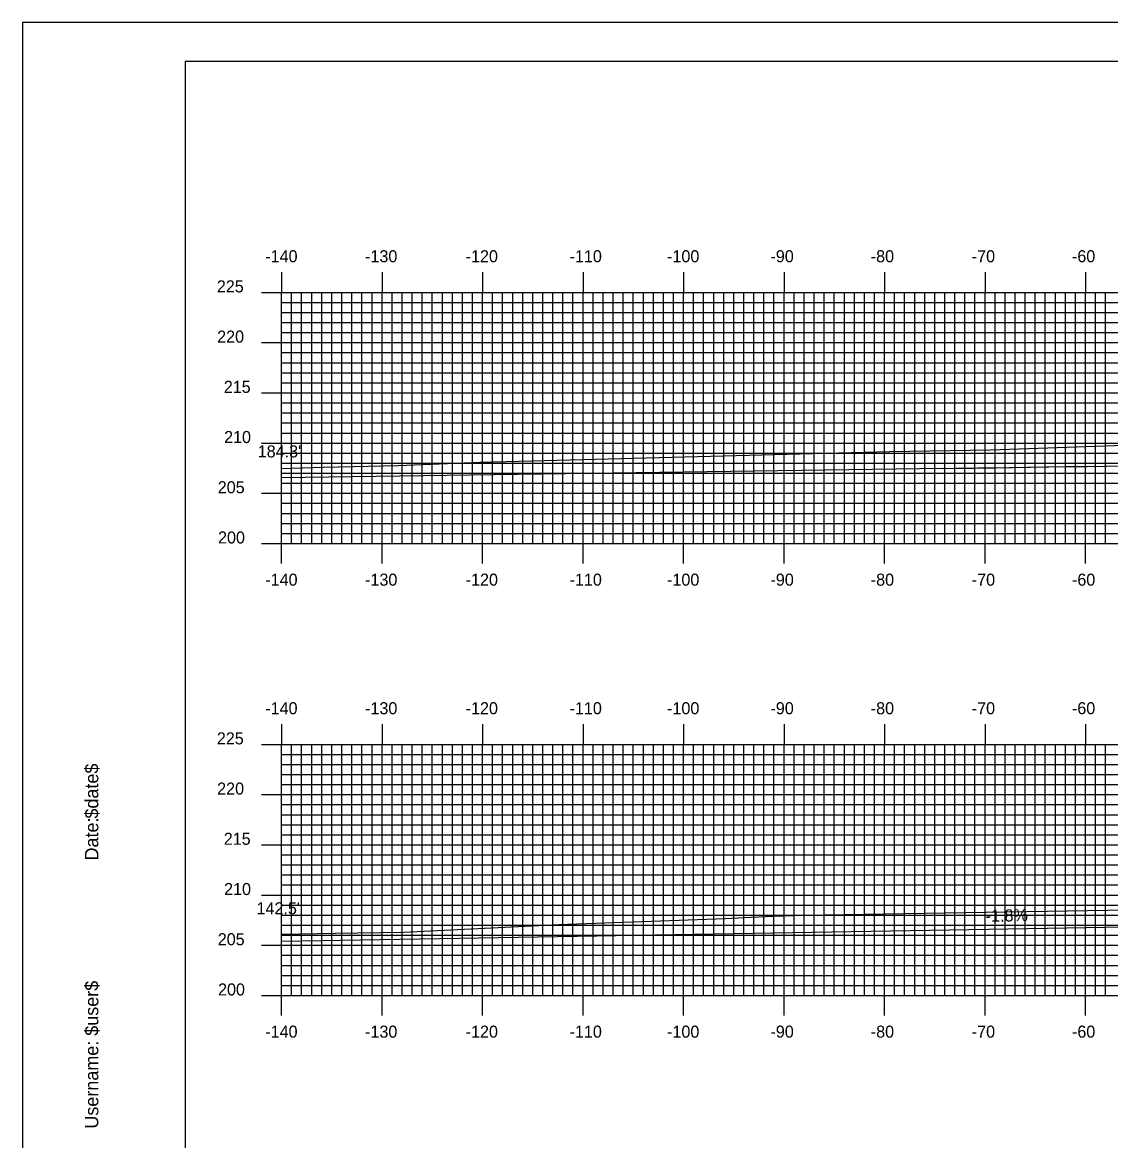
# Model space of a CAD drawing. Extents: x 853316 to 853659, y 364785 to 365005.
# Drawn here: x 853316 to 853424.3, y 364893.8 to 365005.1 of the extents above; entities that cross this region are included whole.
import ezdxf

# ---------------------------------------------------------------- set-up
doc = ezdxf.new("R2010")
doc.units = 0
for name, color, linetype in [('ANNOTATION', 7, 'Continuous'), ('BORDER', 7, 'Continuous'), ('D_Roadway_Centerline', 7, 'Continuous'), ('D_Roadway_FinishedGrade', 7, 'Continuous'), ('D_Roadway_SlopeLines', 7, 'Continuous'), ('D_Text_Standard', 7, 'Continuous'), ('H_V ANNOTATION', 7, 'Continuous'), ('MAJOR', 7, 'Continuous'), ('MINOR', 7, 'Continuous'), ('PLOT BOUNDARY', 7, 'Continuous'), ('S_Roadway_Centerline', 7, 'Continuous')]:
    doc.layers.add(name, color=color, linetype=linetype)

msp = doc.modelspace()

# ---------------------------------------------------------------- linework, layer by layer
at = {"layer": 'BORDER'}
msp.add_lwpolyline([(853332.16, 364791.23), (853652.16, 364791.23), (853652.16, 365001.23), (853332.16, 365001.23)], close=True, dxfattribs=at)
at = {"layer": 'D_Roadway_Centerline'}
msp.add_lwpolyline([(853407.64, 364960.7), (853408.9, 364960.72), (853409.31, 364960.72), (853410.62, 364960.74), (853411, 364960.75), (853412.38, 364960.77), (853412.73, 364960.77), (853414.17, 364960.79), (853414.49, 364960.8), (853416, 364960.82), (853416.29, 364960.83), (853417.87, 364960.85), (853418.12, 364960.85), (853419.77, 364960.88), (853420, 364960.88), (853421.72, 364960.91), (853421.91, 364960.91), (853423.72, 364960.93), (853423.87, 364960.94), (853425.75, 364960.96)], dxfattribs=at)
at = {"layer": 'D_Roadway_FinishedGrade'}
for p, q in [((853407.64, 364960.7), (853341.76, 364959.77)), ((853371.17, 364914.1), (853341.76, 364913.59))]:
    msp.add_line(p, q, dxfattribs=at)
at = {"layer": 'D_Roadway_SlopeLines'}
msp.add_lwpolyline([(853461.39, 364918.94), (853447.17, 364915.41), (853371.17, 364914.1)], dxfattribs=at)
at = {"layer": 'MAJOR'}
for p, q in [((853341.76, 364980.24), (853341.76, 364978.23)), ((853351.76, 364980.24), (853351.76, 364978.23)), ((853361.76, 364980.24), (853361.76, 364978.23)), ((853371.76, 364980.24), (853371.76, 364978.23)), ((853381.76, 364980.24), (853381.76, 364978.23)), ((853391.76, 364980.24), (853391.76, 364978.23)), ((853401.76, 364980.24), (853401.76, 364978.23)), ((853411.76, 364980.24), (853411.76, 364978.23)), ((853421.76, 364980.24), (853421.76, 364978.23)), ((853339.75, 364978.23), (853341.76, 364978.23)), ((853341.76, 364978.23), (853621.76, 364978.23)), ((853341.76, 364953.23), (853341.76, 364978.23)), ((853341.76, 364953.23), (853341.76, 364978.23)), ((853341.76, 364978.23), (853621.76, 364978.23)), ((853351.76, 364953.23), (853351.76, 364978.23)), ((853361.76, 364953.23), (853361.76, 364978.23)), ((853371.76, 364953.23), (853371.76, 364978.23)), ((853381.76, 364953.23), (853381.76, 364978.23)), ((853391.76, 364953.23), (853391.76, 364978.23)), ((853401.76, 364953.23), (853401.76, 364978.23)), ((853411.76, 364953.23), (853411.76, 364978.23)), ((853421.76, 364953.23), (853421.76, 364978.23)), ((853339.75, 364973.23), (853341.76, 364973.23)), ((853341.76, 364973.23), (853621.76, 364973.23)), ((853339.75, 364968.23), (853341.76, 364968.23)), ((853341.76, 364968.23), (853621.76, 364968.23)), ((853339.75, 364963.23), (853341.76, 364963.23)), ((853341.76, 364963.23), (853621.76, 364963.23)), ((853339.75, 364958.23), (853341.76, 364958.23)), ((853341.76, 364958.23), (853621.76, 364958.23)), ((853339.75, 364953.23), (853341.76, 364953.23)), ((853341.76, 364953.23), (853621.76, 364953.23)), ((853341.76, 364953.23), (853621.76, 364953.23)), ((853341.76, 364951.23), (853341.76, 364953.23)), ((853351.76, 364951.23), (853351.76, 364953.23)), ((853361.76, 364951.23), (853361.76, 364953.23)), ((853371.76, 364951.23), (853371.76, 364953.23)), ((853381.76, 364951.23), (853381.76, 364953.23)), ((853391.76, 364951.23), (853391.76, 364953.23)), ((853401.76, 364951.23), (853401.76, 364953.23)), ((853411.76, 364951.23), (853411.76, 364953.23)), ((853421.76, 364951.23), (853421.76, 364953.23)), ((853341.76, 364935.24), (853341.76, 364933.23)), ((853351.76, 364935.24), (853351.76, 364933.23)), ((853361.76, 364935.24), (853361.76, 364933.23)), ((853371.76, 364935.24), (853371.76, 364933.23)), ((853381.76, 364935.24), (853381.76, 364933.23)), ((853391.76, 364935.24), (853391.76, 364933.23)), ((853401.76, 364935.24), (853401.76, 364933.23)), ((853411.76, 364935.24), (853411.76, 364933.23)), ((853421.76, 364935.24), (853421.76, 364933.23)), ((853339.75, 364933.23), (853341.76, 364933.23)), ((853341.76, 364933.23), (853621.76, 364933.23)), ((853341.76, 364908.23), (853341.76, 364933.23)), ((853341.76, 364908.23), (853341.76, 364933.23)), ((853341.76, 364933.23), (853621.76, 364933.23)), ((853351.76, 364908.23), (853351.76, 364933.23)), ((853361.76, 364908.23), (853361.76, 364933.23)), ((853371.76, 364908.23), (853371.76, 364933.23)), ((853381.76, 364908.23), (853381.76, 364933.23)), ((853391.76, 364908.23), (853391.76, 364933.23)), ((853401.76, 364908.23), (853401.76, 364933.23)), ((853411.76, 364908.23), (853411.76, 364933.23)), ((853421.76, 364908.23), (853421.76, 364933.23)), ((853339.75, 364928.23), (853341.76, 364928.23)), ((853341.76, 364928.23), (853621.76, 364928.23)), ((853339.75, 364923.23), (853341.76, 364923.23)), ((853341.76, 364923.23), (853621.76, 364923.23)), ((853339.75, 364918.23), (853341.76, 364918.23)), ((853341.76, 364918.23), (853621.76, 364918.23)), ((853339.75, 364913.23), (853341.76, 364913.23)), ((853341.76, 364913.23), (853621.76, 364913.23)), ((853339.75, 364908.23), (853341.76, 364908.23)), ((853341.76, 364908.23), (853621.76, 364908.23)), ((853341.76, 364908.23), (853621.76, 364908.23)), ((853341.76, 364906.23), (853341.76, 364908.23)), ((853351.76, 364906.23), (853351.76, 364908.23)), ((853361.76, 364906.23), (853361.76, 364908.23)), ((853371.76, 364906.23), (853371.76, 364908.23)), ((853381.76, 364906.23), (853381.76, 364908.23)), ((853391.76, 364906.23), (853391.76, 364908.23)), ((853401.76, 364906.23), (853401.76, 364908.23)), ((853411.76, 364906.23), (853411.76, 364908.23)), ((853421.76, 364906.23), (853421.76, 364908.23))]:
    msp.add_line(p, q, dxfattribs=at)
at = {"layer": 'MINOR'}
for p, q in [((853342.76, 364953.23), (853342.76, 364978.23)), ((853343.76, 364953.23), (853343.76, 364978.23)), ((853344.76, 364953.23), (853344.76, 364978.23)), ((853345.76, 364953.23), (853345.76, 364978.23)), ((853346.76, 364953.23), (853346.76, 364978.23)), ((853347.76, 364953.23), (853347.76, 364978.23)), ((853348.76, 364953.23), (853348.76, 364978.23)), ((853349.76, 364953.23), (853349.76, 364978.23)), ((853350.76, 364953.23), (853350.76, 364978.23)), ((853352.76, 364953.23), (853352.76, 364978.23)), ((853353.76, 364953.23), (853353.76, 364978.23)), ((853354.76, 364953.23), (853354.76, 364978.23)), ((853355.76, 364953.23), (853355.76, 364978.23)), ((853356.76, 364953.23), (853356.76, 364978.23)), ((853357.76, 364953.23), (853357.76, 364978.23)), ((853358.76, 364953.23), (853358.76, 364978.23)), ((853359.76, 364953.23), (853359.76, 364978.23)), ((853360.76, 364953.23), (853360.76, 364978.23)), ((853362.76, 364953.23), (853362.76, 364978.23)), ((853363.76, 364953.23), (853363.76, 364978.23)), ((853364.76, 364953.23), (853364.76, 364978.23)), ((853365.76, 364953.23), (853365.76, 364978.23)), ((853366.76, 364953.23), (853366.76, 364978.23)), ((853367.76, 364953.23), (853367.76, 364978.23)), ((853368.76, 364953.23), (853368.76, 364978.23)), ((853369.76, 364953.23), (853369.76, 364978.23)), ((853370.76, 364953.23), (853370.76, 364978.23)), ((853372.76, 364953.23), (853372.76, 364978.23)), ((853373.76, 364953.23), (853373.76, 364978.23)), ((853374.76, 364953.23), (853374.76, 364978.23)), ((853375.76, 364953.23), (853375.76, 364978.23)), ((853376.76, 364953.23), (853376.76, 364978.23)), ((853377.76, 364953.23), (853377.76, 364978.23)), ((853378.76, 364953.23), (853378.76, 364978.23)), ((853379.76, 364953.23), (853379.76, 364978.23)), ((853380.76, 364953.23), (853380.76, 364978.23)), ((853382.76, 364953.23), (853382.76, 364978.23)), ((853383.76, 364953.23), (853383.76, 364978.23)), ((853384.76, 364953.23), (853384.76, 364978.23)), ((853385.76, 364953.23), (853385.76, 364978.23)), ((853386.76, 364953.23), (853386.76, 364978.23)), ((853387.76, 364953.23), (853387.76, 364978.23)), ((853388.76, 364953.23), (853388.76, 364978.23)), ((853389.76, 364953.23), (853389.76, 364978.23)), ((853390.76, 364953.23), (853390.76, 364978.23)), ((853392.76, 364953.23), (853392.76, 364978.23)), ((853393.76, 364953.23), (853393.76, 364978.23)), ((853394.76, 364953.23), (853394.76, 364978.23)), ((853395.76, 364953.23), (853395.76, 364978.23)), ((853396.76, 364953.23), (853396.76, 364978.23)), ((853397.76, 364953.23), (853397.76, 364978.23)), ((853398.76, 364953.23), (853398.76, 364978.23)), ((853399.76, 364953.23), (853399.76, 364978.23)), ((853400.76, 364953.23), (853400.76, 364978.23)), ((853402.76, 364953.23), (853402.76, 364978.23)), ((853403.76, 364953.23), (853403.76, 364978.23)), ((853404.76, 364953.23), (853404.76, 364978.23)), ((853405.76, 364953.23), (853405.76, 364978.23)), ((853406.76, 364953.23), (853406.76, 364978.23)), ((853407.76, 364953.23), (853407.76, 364978.23)), ((853408.76, 364953.23), (853408.76, 364978.23)), ((853409.76, 364953.23), (853409.76, 364978.23)), ((853410.76, 364953.23), (853410.76, 364978.23)), ((853412.76, 364953.23), (853412.76, 364978.23)), ((853413.76, 364953.23), (853413.76, 364978.23)), ((853414.76, 364953.23), (853414.76, 364978.23)), ((853415.76, 364953.23), (853415.76, 364978.23)), ((853416.76, 364953.23), (853416.76, 364978.23)), ((853417.76, 364953.23), (853417.76, 364978.23)), ((853418.76, 364953.23), (853418.76, 364978.23)), ((853419.76, 364953.23), (853419.76, 364978.23)), ((853420.76, 364953.23), (853420.76, 364978.23)), ((853422.76, 364953.23), (853422.76, 364978.23)), ((853423.76, 364953.23), (853423.76, 364978.23)), ((853341.76, 364977.23), (853621.76, 364977.23)), ((853341.76, 364977.23), (853343.76, 364977.23)), ((853341.76, 364976.23), (853621.76, 364976.23)), ((853341.76, 364976.23), (853343.76, 364976.23)), ((853341.76, 364975.23), (853621.76, 364975.23)), ((853341.76, 364975.23), (853343.76, 364975.23)), ((853341.76, 364974.23), (853621.76, 364974.23)), ((853341.76, 364974.23), (853343.76, 364974.23)), ((853341.76, 364972.23), (853621.76, 364972.23)), ((853341.76, 364972.23), (853343.76, 364972.23)), ((853341.76, 364971.23), (853621.76, 364971.23)), ((853341.76, 364971.23), (853343.76, 364971.23)), ((853341.76, 364970.23), (853621.76, 364970.23)), ((853341.76, 364970.23), (853343.76, 364970.23)), ((853341.76, 364969.23), (853621.76, 364969.23)), ((853341.76, 364969.23), (853343.76, 364969.23)), ((853341.76, 364967.23), (853621.76, 364967.23)), ((853341.76, 364967.23), (853343.76, 364967.23)), ((853341.76, 364966.23), (853621.76, 364966.23)), ((853341.76, 364966.23), (853343.76, 364966.23)), ((853341.76, 364965.23), (853621.76, 364965.23)), ((853341.76, 364965.23), (853343.76, 364965.23)), ((853341.76, 364964.23), (853621.76, 364964.23)), ((853341.76, 364964.23), (853343.76, 364964.23)), ((853341.76, 364962.23), (853621.76, 364962.23)), ((853341.76, 364962.23), (853343.76, 364962.23)), ((853341.76, 364961.23), (853621.76, 364961.23)), ((853341.76, 364961.23), (853343.76, 364961.23)), ((853341.76, 364960.23), (853621.76, 364960.23)), ((853341.76, 364960.23), (853343.76, 364960.23)), ((853341.76, 364959.23), (853621.76, 364959.23)), ((853341.76, 364959.23), (853343.76, 364959.23)), ((853341.76, 364957.23), (853621.76, 364957.23)), ((853341.76, 364957.23), (853343.76, 364957.23)), ((853341.76, 364956.23), (853621.76, 364956.23)), ((853341.76, 364956.23), (853343.76, 364956.23)), ((853341.76, 364955.23), (853621.76, 364955.23)), ((853341.76, 364955.23), (853343.76, 364955.23)), ((853341.76, 364954.23), (853621.76, 364954.23)), ((853341.76, 364954.23), (853343.76, 364954.23)), ((853342.76, 364908.23), (853342.76, 364933.23)), ((853343.76, 364908.23), (853343.76, 364933.23)), ((853344.76, 364908.23), (853344.76, 364933.23)), ((853345.76, 364908.23), (853345.76, 364933.23)), ((853346.76, 364908.23), (853346.76, 364933.23)), ((853347.76, 364908.23), (853347.76, 364933.23)), ((853348.76, 364908.23), (853348.76, 364933.23)), ((853349.76, 364908.23), (853349.76, 364933.23)), ((853350.76, 364908.23), (853350.76, 364933.23)), ((853352.76, 364908.23), (853352.76, 364933.23)), ((853353.76, 364908.23), (853353.76, 364933.23)), ((853354.76, 364908.23), (853354.76, 364933.23)), ((853355.76, 364908.23), (853355.76, 364933.23)), ((853356.76, 364908.23), (853356.76, 364933.23)), ((853357.76, 364908.23), (853357.76, 364933.23)), ((853358.76, 364908.23), (853358.76, 364933.23)), ((853359.76, 364908.23), (853359.76, 364933.23)), ((853360.76, 364908.23), (853360.76, 364933.23)), ((853362.76, 364908.23), (853362.76, 364933.23)), ((853363.76, 364908.23), (853363.76, 364933.23)), ((853364.76, 364908.23), (853364.76, 364933.23)), ((853365.76, 364908.23), (853365.76, 364933.23)), ((853366.76, 364908.23), (853366.76, 364933.23)), ((853367.76, 364908.23), (853367.76, 364933.23)), ((853368.76, 364908.23), (853368.76, 364933.23)), ((853369.76, 364908.23), (853369.76, 364933.23)), ((853370.76, 364908.23), (853370.76, 364933.23)), ((853372.76, 364908.23), (853372.76, 364933.23)), ((853373.76, 364908.23), (853373.76, 364933.23)), ((853374.76, 364908.23), (853374.76, 364933.23)), ((853375.76, 364908.23), (853375.76, 364933.23)), ((853376.76, 364908.23), (853376.76, 364933.23)), ((853377.76, 364908.23), (853377.76, 364933.23)), ((853378.76, 364908.23), (853378.76, 364933.23)), ((853379.76, 364908.23), (853379.76, 364933.23)), ((853380.76, 364908.23), (853380.76, 364933.23)), ((853382.76, 364908.23), (853382.76, 364933.23)), ((853383.76, 364908.23), (853383.76, 364933.23)), ((853384.76, 364908.23), (853384.76, 364933.23)), ((853385.76, 364908.23), (853385.76, 364933.23)), ((853386.76, 364908.23), (853386.76, 364933.23)), ((853387.76, 364908.23), (853387.76, 364933.23)), ((853388.76, 364908.23), (853388.76, 364933.23)), ((853389.76, 364908.23), (853389.76, 364933.23)), ((853390.76, 364908.23), (853390.76, 364933.23)), ((853392.76, 364908.23), (853392.76, 364933.23)), ((853393.76, 364908.23), (853393.76, 364933.23)), ((853394.76, 364908.23), (853394.76, 364933.23)), ((853395.76, 364908.23), (853395.76, 364933.23)), ((853396.76, 364908.23), (853396.76, 364933.23)), ((853397.76, 364908.23), (853397.76, 364933.23)), ((853398.76, 364908.23), (853398.76, 364933.23)), ((853399.76, 364908.23), (853399.76, 364933.23)), ((853400.76, 364908.23), (853400.76, 364933.23)), ((853402.76, 364908.23), (853402.76, 364933.23)), ((853403.76, 364908.23), (853403.76, 364933.23)), ((853404.76, 364908.23), (853404.76, 364933.23)), ((853405.76, 364908.23), (853405.76, 364933.23)), ((853406.76, 364908.23), (853406.76, 364933.23)), ((853407.76, 364908.23), (853407.76, 364933.23)), ((853408.76, 364908.23), (853408.76, 364933.23)), ((853409.76, 364908.23), (853409.76, 364933.23)), ((853410.76, 364908.23), (853410.76, 364933.23)), ((853412.76, 364908.23), (853412.76, 364933.23)), ((853413.76, 364908.23), (853413.76, 364933.23)), ((853414.76, 364908.23), (853414.76, 364933.23)), ((853415.76, 364908.23), (853415.76, 364933.23)), ((853416.76, 364908.23), (853416.76, 364933.23)), ((853417.76, 364908.23), (853417.76, 364933.23)), ((853418.76, 364908.23), (853418.76, 364933.23)), ((853419.76, 364908.23), (853419.76, 364933.23)), ((853420.76, 364908.23), (853420.76, 364933.23)), ((853422.76, 364908.23), (853422.76, 364933.23)), ((853423.76, 364908.23), (853423.76, 364933.23)), ((853341.76, 364932.23), (853621.76, 364932.23)), ((853341.76, 364932.23), (853343.76, 364932.23)), ((853341.76, 364931.23), (853621.76, 364931.23)), ((853341.76, 364931.23), (853343.76, 364931.23)), ((853341.76, 364930.23), (853621.76, 364930.23)), ((853341.76, 364930.23), (853343.76, 364930.23)), ((853341.76, 364929.23), (853621.76, 364929.23)), ((853341.76, 364929.23), (853343.76, 364929.23)), ((853341.76, 364927.23), (853621.76, 364927.23)), ((853341.76, 364927.23), (853343.76, 364927.23)), ((853341.76, 364926.23), (853621.76, 364926.23)), ((853341.76, 364926.23), (853343.76, 364926.23)), ((853341.76, 364925.23), (853621.76, 364925.23)), ((853341.76, 364925.23), (853343.76, 364925.23)), ((853341.76, 364924.23), (853621.76, 364924.23)), ((853341.76, 364924.23), (853343.76, 364924.23)), ((853341.76, 364922.23), (853621.76, 364922.23)), ((853341.76, 364922.23), (853343.76, 364922.23)), ((853341.76, 364921.23), (853621.76, 364921.23)), ((853341.76, 364921.23), (853343.76, 364921.23)), ((853341.76, 364920.23), (853621.76, 364920.23)), ((853341.76, 364920.23), (853343.76, 364920.23)), ((853341.76, 364919.23), (853621.76, 364919.23)), ((853341.76, 364919.23), (853343.76, 364919.23)), ((853341.76, 364917.23), (853621.76, 364917.23)), ((853341.76, 364917.23), (853343.76, 364917.23)), ((853341.76, 364916.23), (853621.76, 364916.23)), ((853341.76, 364916.23), (853343.76, 364916.23)), ((853341.76, 364915.23), (853621.76, 364915.23)), ((853341.76, 364915.23), (853343.76, 364915.23)), ((853341.76, 364914.23), (853621.76, 364914.23)), ((853341.76, 364914.23), (853343.76, 364914.23)), ((853341.76, 364912.23), (853621.76, 364912.23)), ((853341.76, 364912.23), (853343.76, 364912.23)), ((853341.76, 364911.23), (853621.76, 364911.23)), ((853341.76, 364911.23), (853343.76, 364911.23)), ((853341.76, 364910.23), (853621.76, 364910.23)), ((853341.76, 364910.23), (853343.76, 364910.23)), ((853341.76, 364909.23), (853621.76, 364909.23)), ((853341.76, 364909.23), (853343.76, 364909.23))]:
    msp.add_line(p, q, dxfattribs=at)
at = {"layer": 'PLOT BOUNDARY'}
msp.add_lwpolyline([(853315.97, 364785.11), (853655.97, 364785.11), (853655.97, 365005.11), (853315.97, 365005.11)], close=True, dxfattribs=at)
at = {"layer": 'S_Roadway_Centerline'}
for points in [[(853341.76, 364960.71), (853345.93, 364960.83), (853353.35, 364961.01), (853361.55, 364961.33), (853402.27, 364962.38), (853412.31, 364962.57), (853439.83, 364963.53), (853463.65, 364964.4), (853479.24, 364964.85), (853485.19, 364965.12), (853498.57, 364965.58), (853509.74, 364965.76), (853537.83, 364967.42), (853541.41, 364967.63), (853545.3, 364967.83), (853560.67, 364968.6), (853562.25, 364968.66), (853577.65, 364969.22), (853583.69, 364969.65), (853594.37, 364970.31), (853607.63, 364971.07), (853621.76, 364971.89)], [(853341.76, 364914.32), (853347.1, 364914.42), (853353.88, 364914.55), (853369.34, 364915.29), (853370.22, 364915.33), (853385.95, 364915.91), (853387.75, 364916), (853390.71, 364916.13), (853393.68, 364916.23), (853430.05, 364916.84), (853444.48, 364917.05), (853452.3, 364917.5), (853506.17, 364918.85), (853506.72, 364918.86), (853507.22, 364918.88), (853507.88, 364918.91), (853540.24, 364920.6), (853555.34, 364921.1), (853558.6, 364921.29), (853584.78, 364924.26), (853591.18, 364924.71), (853605.32, 364925.33), (853607.63, 364925.51), (853621.76, 364926.36)]]:
    msp.add_lwpolyline(points, dxfattribs=at)

# ---------------------------------------------------------------- texts
at = {"layer": 'ANNOTATION'}
msp.add_text('-1.8%', height=1.2, rotation=1.0514, dxfattribs=at).set_placement((853411.84, 364915.56))
at = {"layer": 'BORDER'}
for s, p in [('$date$', (853323.53, 364925.84)), ('Date:', (853323.53, 364921.67)), ('$user$', (853323.53, 364904.22)), ('Username:', (853323.53, 364894.97))]:
    msp.add_text(s, height=1.339, rotation=90, dxfattribs=at).set_placement(p)
at = {"layer": 'D_Text_Standard'}
for s, p in [("184.3'", (853339.39, 364961.8)), ("142.5'", (853339.27, 364916.31))]:
    msp.add_text(s, height=1.2, dxfattribs=at).set_placement(p)
at = {"layer": 'H_V ANNOTATION'}
for s, p in [('-140', (853340.14, 364981.23)), ('-130', (853350.07, 364981.23)), ('-120', (853360.08, 364981.23)), ('-110', (853370.42, 364981.23)), ('-100', (853380.12, 364981.23)), ('-90', (853390.41, 364981.23)), ('-80', (853400.39, 364981.23)), ('-70', (853410.44, 364981.23)), ('-60', (853420.41, 364981.23)), ('225', (853335.32, 364978.23)), ('220', (853335.35, 364973.23)), ('215', (853336.01, 364968.23)), ('210', (853336.04, 364963.23)), ('205', (853335.41, 364958.23)), ('200', (853335.44, 364953.23)), ('-140', (853340.14, 364949.03)), ('-130', (853350.07, 364949.03)), ('-120', (853360.08, 364949.03)), ('-110', (853370.42, 364949.03)), ('-100', (853380.12, 364949.03)), ('-90', (853390.41, 364949.03)), ('-80', (853400.39, 364949.03)), ('-70', (853410.44, 364949.03)), ('-60', (853420.41, 364949.03)), ('-140', (853340.14, 364936.23)), ('-130', (853350.07, 364936.23)), ('-120', (853360.08, 364936.23)), ('-110', (853370.42, 364936.23)), ('-100', (853380.12, 364936.23)), ('-90', (853390.41, 364936.23)), ('-80', (853400.39, 364936.23)), ('-70', (853410.44, 364936.23)), ('-60', (853420.41, 364936.23)), ('225', (853335.32, 364933.23)), ('220', (853335.35, 364928.23)), ('215', (853336.01, 364923.23)), ('210', (853336.04, 364918.23)), ('205', (853335.41, 364913.23)), ('200', (853335.44, 364908.23)), ('-140', (853340.14, 364904.03)), ('-130', (853350.07, 364904.03)), ('-120', (853360.08, 364904.03)), ('-110', (853370.42, 364904.03)), ('-100', (853380.12, 364904.03)), ('-90', (853390.41, 364904.03)), ('-80', (853400.39, 364904.03)), ('-70', (853410.44, 364904.03)), ('-60', (853420.41, 364904.03))]:
    msp.add_text(s, height=1.2, dxfattribs=at).set_placement(p)
at = {"layer": 'MAJOR'}
for p in [(853341.75, 364953.23), (853341.75, 364908.23)]:
    msp.add_text('-', height=0.012, dxfattribs=at).set_placement(p)

doc.saveas('drawing.dxf')
